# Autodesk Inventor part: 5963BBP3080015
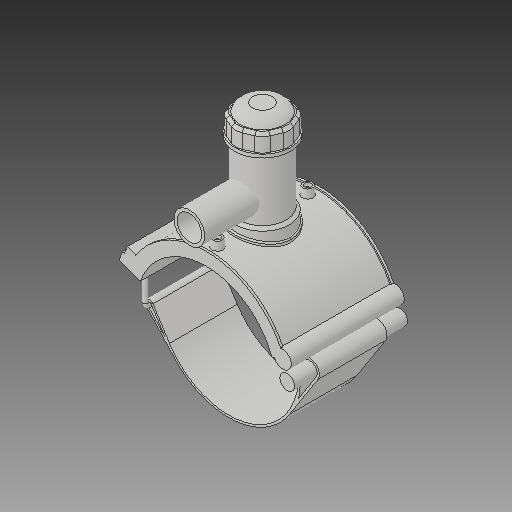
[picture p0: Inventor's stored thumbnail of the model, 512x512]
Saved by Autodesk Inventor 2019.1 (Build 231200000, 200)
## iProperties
Created: 2017-07
Part Number: 5963BBP3080015
Material: Generic
Description: PLASSON TAPPING SADDLE 8''IPS x 1 1/2''IPS
Document SubType Name: Modeling
Designer: KIM
Density: 1 g/cm^3
Appearance: Default
Author: KIM
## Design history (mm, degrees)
derived "5963BBP_5963BUP.ipt"
feature "Solid1::5963BBP_5963BUP.ipt"
feature "Solid2::5963BBP_5963BUP.ipt"
feature "Solid3::5963BBP_5963BUP.ipt"
tag "TaggingFeature1"
body "Solid1"
body "Solid2"
body "Solid3"
other parameters: "d0" = 218.7, "d2" = 269.748, "d3" = 54.675, "d4" = 176.022, "d5" = 0, "d6" = 0.1, "d8" = 0, "d19" = 6, "d20" = 6, "d21" = 105.6132, "d23" = 0, "d24" = 52.8066, "d26" = 0, "d27" = 3, "d28" = 3, "d29" = 3, "d30" = 72.9, "d31" = 6, "d32" = 0, "d33" = 0, "d34" = 0.6, "d40" = 131.91984, "d41" = 87.48, "d43" = 0, "d45" = 0, "d47" = 232.4592, "d70" = 15, "d72" = 0, "d73" = 6, "d75" = 5, "d76" = 0, "d77" = 10.935, "d78" = 139.35, "d79" = 15, "d80" = 70.4088, "d82" = 5 deg, "d84" = 4, "d85" = 14, "d86" = 0, "d87" = 3, "d88" = 0, "d89" = 1, "d90" = 1, "d91" = 140.8176, "d92" = 0, "d93" = 0.5, "d94" = 115.10526, "d96" = 258.76584, "d97" = 3.52044, "d98" = 0, "d102" = 2.187, "d120" = 140 deg, "d121" = 24.228, "d122" = 20 deg, "d123" = 507.384, "d124" = 152.2152, "d126" = 0, "d143" = 225.261, "d145" = 26.91692, "d149" = 3.2805, "d150" = 29.60862, "d153" = 176.022, "d154" = 0, "d156" = 126.846, "d157" = 160 deg, "d159" = 6.9984, "d161" = 3.2805, "d162" = 105.6132, "d163" = 0, "d164" = 109.35, "d167" = 21.87, "d168" = 123.7522, "d170" = 3.2805, "d172" = 0, "d173" = 1, "d175" = 109.35, "d176" = 20 deg, "d177" = 15.309, "d178" = 34.992, "d180" = 0, "d183" = 13.9968, "d184" = 12.2472, "d185" = 57.20715, "d186" = 57.20715, "d187" = 126.846, "d188" = 10.4976, "d189" = 15.309, "d190" = 0, "d191" = 190.269, "d193" = 6.9984, "d194" = 6.16077, "d195" = 90 deg, "d197" = 0, "d199" = 0, "d200" = 17.496, "d202" = 0, "d203" = 177.038, "d204" = 83.106, "d205" = 61.236, "d206" = 74.358, "d207" = 132.7785, "d208" = 138.08964, "d209" = 164.64534, "d210" = 75.2328, "d211" = 87.48, "d212" = 69.984, "d213" = 36.8766, "d216" = 0, "d217" = 21.87, "d218" = 21.87, "d219" = 4.374, "d222" = 218.7, "d224" = 0, "d225" = 65.024, "d226" = 48.1, "d227" = 38.48, "d228" = 114.046, "d230" = 4.374, "d_" = 218.7, "B_" = 179.832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
